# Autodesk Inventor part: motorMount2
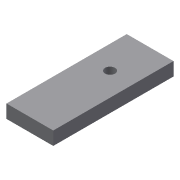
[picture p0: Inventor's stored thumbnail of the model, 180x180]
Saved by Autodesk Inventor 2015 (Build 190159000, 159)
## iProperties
Created: 2016-07
Part Number: motorMount2
Material: EIFS, Exterior Insulation
Document SubType Name: Modeling
Designer: user
Density: 0.023 g/cm^3
Appearance: Gray
Author: user
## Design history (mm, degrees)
sketch "Sketch1"
  geometry: L1 (0, 0)-(-22.225, 0); L2 (-22.225, 0)-(-22.225, -57.15); L3 (-22.225, -57.15)-(0, -57.15); L4 (0, -57.15)-(0, 0); C1 r 2.381 at (-11.113, -38.1)
  constraints: 8 end point, 2 parallel, 1 centre point, 1 horizontal, 1 perpendicular
  dimensions: "d0" = 22.225 distance of L3.end L2.end; "d1" = 57.15 distance of L2.end L1.end; "d2" = 4.7625 diameter of C1
extrude "Extrusion1" new body sketch "Sketch1" distance "d3" = 6.35; taper "d4" = 0 deg
body "Solid1"
